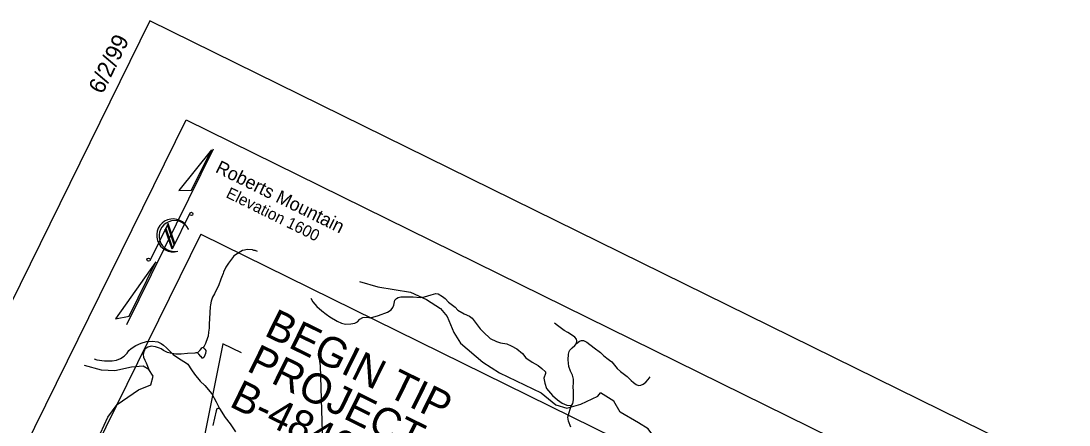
# Model space of a CAD drawing. Extents: x 1428428 to 1430511, y 857911 to 859585.
# Drawn here: x 1429036.9 to 1429384.6, y 859450.7 to 859584.7 of the extents above; entities that cross this region are included whole.
import ezdxf

# ---------------------------------------------------------------- set-up
doc = ezdxf.new("R2010")
doc.units = 0
for name, color, linetype in [('CTL Sheet Border CELL', 7, 'Continuous'), ('Default', 7, 'Continuous'), ('Exist Hydrographic Creek Single Shore', 7, 'Continuous'), ('Exist Hydrographic Misc Water Feature', 7, 'Continuous'), ('Exist Road Non-System Type 51', 7, 'Continuous'), ('Exist Road Secondary Type 51 Attributed', 7, 'Continuous'), ('Scratch_Level_3', 7, 'Continuous'), ('Sheet North Arrow CELL', 7, 'Continuous'), ('Sheet Title CELL', 7, 'Continuous')]:
    doc.layers.add(name, color=color, linetype=linetype)

msp = doc.modelspace()

# ---------------------------------------------------------------- linework, layer by layer
at = {"layer": 'CTL Sheet Border CELL'}
msp.add_lwpolyline([(1430484.04, 858893.65), (1429079.63, 859584.7), (1428595.9, 858601.62), (1430000.31, 857910.57)], close=True, dxfattribs=at)
at = {"layer": 'Default'}
for p, q in [((1429103.82, 859477.64), (1429088.02, 859398.35)), ((1429110, 859474.6), (1429103.82, 859477.64))]:
    msp.add_line(p, q, dxfattribs=at)
at = {"layer": 'Exist Hydrographic Creek Single Shore'}
for points in [[(1429060.78, 859442.66), (1429065.69, 859453.28), (1429068.79, 859457.44), (1429075.85, 859462.35), (1429079.94, 859463.96), (1429080.69, 859466.9), (1429079.25, 859469.13), (1429077.38, 859470.24), (1429073.51, 859469.86), (1429068.03, 859468.67), (1429063.62, 859468.87), (1429057.93, 859470.39)], [(1429241.72, 859451.38), (1429235.67, 859454.99), (1429233.61, 859458.64), (1429229.17, 859461.31)]]:
    msp.add_lwpolyline(points, dxfattribs=at)
at = {"layer": 'Exist Hydrographic Misc Water Feature'}
for points in [[(1429115.39, 859508.24), (1429114.61, 859508.55), (1429114.15, 859508.61), (1429113.68, 859508.77), (1429111.93, 859508.86), (1429111, 859508.72), (1429110.35, 859508.51), (1429109.82, 859508.25), (1429107.36, 859506.64), (1429107.34, 859506.53), (1429105.68, 859504.33), (1429104.87, 859503.07), (1429104.08, 859501.36), (1429103.95, 859500.94), (1429103.37, 859499.66), (1429103.24, 859499.05), (1429102.45, 859496.84), (1429101.65, 859495.46), (1429101.03, 859494.21), (1429100.38, 859493.05), (1429100.02, 859491.8), (1429099.75, 859490.59), (1429099.67, 859489.91), (1429099.56, 859487.98), (1429099.49, 859487.84), (1429099.46, 859486.05), (1429099.29, 859484.16), (1429099.27, 859482.84), (1429099.14, 859481.44), (1429098.94, 859480.19), (1429098.79, 859479.55), (1429098.12, 859477.73), (1429097.68, 859476.88), (1429097.31, 859476.36)], [(1429149.21, 859498.31), (1429155.23, 859496.53), (1429166.16, 859494.79), (1429171.42, 859492.29), (1429176.07, 859489.29), (1429178.28, 859486.67), (1429180.45, 859481.42), (1429182.7, 859477.81), (1429190.15, 859471.52), (1429195.64, 859467.94), (1429209.5, 859461.36), (1429214.37, 859457.36), (1429217.93, 859456.26), (1429222.59, 859457.62), (1429228.27, 859460.29), (1429229.17, 859461.31)], [(1429095.45, 859474.61), (1429094.93, 859474.61), (1429094.57, 859474.53), (1429092.12, 859474.39), (1429090.04, 859474.21), (1429088.27, 859474.2), (1429086.43, 859474.48), (1429085.49, 859474.74), (1429084.21, 859475.41), (1429083.42, 859475.96), (1429082.83, 859476.21), (1429081.55, 859476.61), (1429080.07, 859476.88), (1429078.93, 859476.54), (1429077.96, 859475.86), (1429077.48, 859474.58), (1429077.47, 859474.04), (1429077.58, 859473.22), (1429077.94, 859472.18), (1429078.39, 859471.31), (1429079.25, 859469.13)], [(1429097.31, 859476.36), (1429096.95, 859476.26), (1429096.63, 859476.07), (1429096.26, 859475.54), (1429096.12, 859475.44), (1429095.97, 859475.15), (1429095.45, 859474.61)], [(1429097.31, 859476.36), (1429097.88, 859475.87), (1429098.17, 859475.41), (1429098.24, 859475.19), (1429098.1, 859474.4), (1429097.88, 859473.8), (1429097.51, 859473.09), (1429097.19, 859472.9), (1429097.04, 859472.88), (1429096.66, 859473.35), (1429096.52, 859473.43), (1429095.92, 859474.19), (1429095.78, 859474.26), (1429095.45, 859474.61)], [(1429097.34, 859398.23), (1429113.3, 859398.27), (1429116.3, 859400.49), (1429118.07, 859405.34), (1429117.98, 859414.26), (1429118.45, 859417.71), (1429121.28, 859423.19), (1429128.2, 859427.52), (1429130.78, 859430.32), (1429134.86, 859438.19), (1429136.92, 859448.36), (1429136.23, 859470.29), (1429135.95, 859472.66)], [(1429260.56, 859416.77), (1429260.41, 859426.22), (1429258.6, 859431.82), (1429255.93, 859436.45), (1429248.85, 859444.18), (1429245, 859449.43), (1429241.72, 859451.38)]]:
    msp.add_lwpolyline(points, dxfattribs=at)
at = {"layer": 'Exist Road Non-System Type 51'}
for points in [[(1429133.01, 859492.73), (1429133.69, 859491.5), (1429135.05, 859490.04), (1429136.73, 859488.52), (1429138.13, 859487.44), (1429139.38, 859486.57), (1429141.83, 859485.12), (1429143.27, 859484.41), (1429144.54, 859484.18), (1429146.32, 859484.29), (1429147.63, 859484.44), (1429148.48, 859484.86), (1429149.31, 859485.74), (1429150.3, 859486.35), (1429151.57, 859486.41), (1429152.84, 859486.28), (1429155.44, 859487.04), (1429158.45, 859488.13), (1429159.7, 859488.85), (1429160.27, 859489.61), (1429160.62, 859490.43), (1429160.93, 859492.06), (1429161.51, 859492.64), (1429162.02, 859492.98), (1429162.95, 859493.16), (1429166.96, 859493.17), (1429169.31, 859493.01), (1429170.75, 859493.24), (1429171.84, 859493.54), (1429172.91, 859493.81), (1429174.5, 859494.31), (1429175.27, 859494.18), (1429176.73, 859493.32), (1429177.65, 859492.67), (1429178.75, 859491.48), (1429180.96, 859489.75), (1429181.8, 859488.79), (1429183.89, 859487.61), (1429185.67, 859486.79), (1429186.58, 859486.14), (1429189.27, 859482.54), (1429190.32, 859481.48), (1429192.54, 859479.35), (1429194.61, 859478.33), (1429195.94, 859477.92), (1429198.09, 859477.56), (1429199.54, 859476.89), (1429201.34, 859475.91), (1429203.31, 859474.35), (1429204.39, 859472.93), (1429206.48, 859471.55), (1429208.47, 859470.37), (1429209.71, 859469.37), (1429210.89, 859468.34), (1429210.93, 859467.73), (1429210.33, 859466.19), (1429210.63, 859464.61), (1429211.24, 859462.82), (1429213.26, 859460.49), (1429214.9, 859458.99), (1429216.47, 859457.97), (1429217.92, 859457.31), (1429219.55, 859457.2)], [(1429221.23, 859477.73), (1429221.25, 859478.55), (1429221.13, 859479.11), (1429220.63, 859479.8), (1429219.89, 859480.41), (1429218.32, 859481.33), (1429217.14, 859482.06), (1429214.83, 859483.7), (1429213.89, 859484.5)], [(1429220.6, 859477.02), (1429221.23, 859477.73)], [(1429221.23, 859477.73), (1429222.22, 859478.53), (1429222.81, 859478.73), (1429223.55, 859478.72), (1429224.56, 859478.17), (1429227.08, 859476.24), (1429229.13, 859474.78), (1429230.13, 859473.7), (1429231.21, 859472.87), (1429232.18, 859472.24), (1429232.92, 859471.63), (1429234.66, 859469.43), (1429235.82, 859468.47), (1429238.01, 859466.8), (1429239.35, 859465.39), (1429240.07, 859464.74), (1429240.97, 859464.15), (1429241.78, 859463.8), (1429242.5, 859463.85), (1429243.27, 859464.21), (1429244.14, 859464.87), (1429244.91, 859465.83), (1429245.64, 859466.61)], [(1429102.78, 859456.11), (1429102.14, 859456.17), (1429101.81, 859456.01), (1429101.61, 859455.35), (1429100.56, 859450.52)]]:
    msp.add_lwpolyline(points, dxfattribs=at)
at = {"layer": 'Exist Road Secondary Type 51 Attributed'}
for points in [[(1429061.12, 859472.64), (1429062.01, 859472.32), (1429064.61, 859472.02), (1429067.14, 859471.98), (1429068.61, 859472.23), (1429069.92, 859472.78), (1429071.07, 859473.53), (1429072.12, 859474.51), (1429072.67, 859475.41), (1429073.4, 859476.06), (1429075.04, 859477.02), (1429076.75, 859477.83), (1429078.51, 859478.35), (1429080.41, 859478.47), (1429082.29, 859478.26), (1429083.36, 859477.69), (1429084.16, 859477.19), (1429085.12, 859476.3), (1429087.34, 859474.12), (1429089.46, 859472.63), (1429091.41, 859471.4), (1429092.2, 859470.87), (1429093.44, 859469.02)], [(1429219.26, 859449.92), (1429218.56, 859451.96), (1429218.27, 859453.24), (1429218.55, 859454.1), (1429219.35, 859456.67), (1429219.97, 859457.8), (1429220.21, 859459), (1429220.13, 859461.88), (1429220.02, 859463.32), (1429220.23, 859464.68), (1429220.21, 859465.87), (1429219.87, 859467.22), (1429219.19, 859468.59), (1429218.62, 859470.12), (1429218.42, 859472.3), (1429218.48, 859474.16), (1429218.74, 859475.07), (1429219.01, 859475.54), (1429219.72, 859476.26), (1429220.6, 859477.02)], [(1429093.44, 859469.02), (1429094.49, 859467.49), (1429096.31, 859465.17), (1429097.87, 859463.84), (1429100.15, 859460.99), (1429101.68, 859458.32), (1429102.78, 859456.11), (1429104.62, 859453.21), (1429106.31, 859451.07), (1429108.1, 859448.46)]]:
    msp.add_lwpolyline(points, dxfattribs=at)
at = {"layer": 'Scratch_Level_3'}
for q in [(1428739.64, 858788.69), (1429536.95, 859297.33)]:
    msp.add_line((1429096.55, 859514.03), q, dxfattribs=at)
at = {"layer": 'Sheet North Arrow CELL'}
for p, q in [((1429072.02, 859484), (1429100.72, 859542.32)), ((1429092.93, 859520.94), (1429087.04, 859508.97)), ((1429085.69, 859517.49), (1429079.7, 859505.33)), ((1429087.04, 859508.97), (1429084.77, 859515.63)), ((1429085.47, 859517.05), (1429084.94, 859515.96)), ((1429087.2, 859509.31), (1429084.94, 859515.96)), ((1429084.94, 859515.96), (1429087.2, 859509.31)), ((1429087.74, 859510.4), (1429085.47, 859517.05)), ((1429087.96, 859510.84), (1429085.69, 859517.49)), ((1429092.38, 859515.67), (1429092.42, 859515.6)), ((1429087.2, 859509.31), (1429087.74, 859510.4))]:
    msp.add_line(p, q, dxfattribs=at)
for points in [[(1429100.06, 859542.01), (1429089.28, 859528.5), (1429093.44, 859528.55)], [(1429081.65, 859504.78), (1429068.24, 859485.86), (1429072.82, 859486.83)]]:
    msp.add_lwpolyline(points, close=True, dxfattribs=at)
for centre in [(1429093.4, 859520.7), (1429079.22, 859505.54)]:
    msp.add_circle(centre, 0.53, dxfattribs=at)
for centre, radius, start, end in [((1429087.35, 859513.58), 5.46, 21.6401, 286.1942), ((1429087.82, 859513.35), 5.12, 26.8952, 282.4288)]:
    msp.add_arc(centre, radius, start, end, dxfattribs=at)
at = {"layer": 'Sheet Title CELL'}
for p, q in [((1428950.38, 859264.79), (1429091.66, 859551.91)), ((1429091.66, 859551.91), (1429369.81, 859415.05))]:
    msp.add_line(p, q, dxfattribs=at)

# ---------------------------------------------------------------- texts
at = {"layer": 'CTL Sheet Border CELL'}
msp.add_text('6/2/99', height=5.478, rotation=63.8001, dxfattribs=at).set_placement((1429063.92, 859560.17))
at = {"layer": 'Default'}
for s, height, p in [('Roberts Mountain', 4.4, (1429101.09, 859534.66)), ('Elevation 1600', 3.8, (1429104.6, 859526.32)), ('BEGIN TIP', 10, (1429117.22, 859480.56)), ('PROJECT', 10, (1429111.43, 859468.8)), ('B-4846', 10, (1429105.64, 859457.03))]:
    msp.add_text(s, height=height, rotation=333.8001, dxfattribs=at).set_placement(p)

doc.saveas('drawing.dxf')
